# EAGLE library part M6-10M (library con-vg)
CONNECTOR male, 6 pins + 10 coax type C, rows ABC, grid 2.54 mm
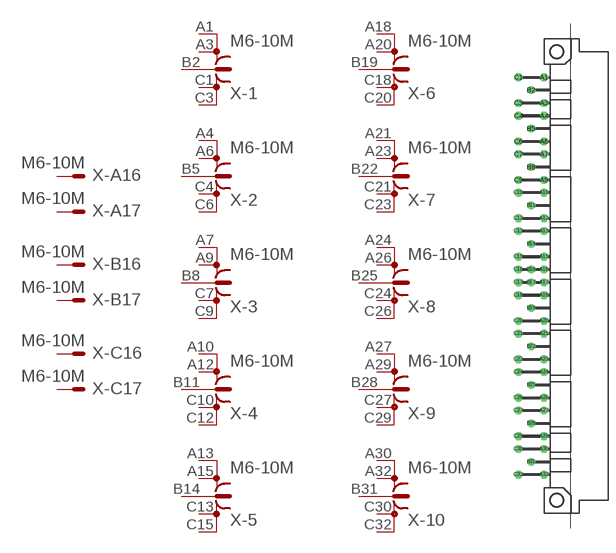
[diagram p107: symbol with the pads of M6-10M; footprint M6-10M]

Designator prefix X; gates -A16=MVAL -A17=MVAL -B16=MVAL -B17=MVAL -C16=MVAL -C17=MVAL -1=COAX -2=COAX -3=COAX -4=COAX -5=COAX -6=COAX -7=COAX -8=COAX -9=COAX -10=COAX

## M6-10M  [M6-10M]
A1  -1:S1  pas
A3  -1:S2  pas
A4  -2:S1  pas
A6  -2:S2  pas
A7  -3:S1  pas
A9  -3:S2  pas
A10  -4:S1  pas
A12  -4:S2  pas
A13  -5:S1  pas
A15  -5:S2  pas
A16  -A16:S  pas
A17  -A17:S  pas
A18  -6:S1  pas
A20  -6:S2  pas
A21  -7:S1  pas
A23  -7:S2  pas
A24  -8:S1  pas
A26  -8:S2  pas
A27  -9:S1  pas
A29  -9:S2  pas
A30  -10:S1  pas
A32  -10:S2  pas
B2  -1:S  pas
B5  -2:S  pas
B8  -3:S  pas
B11  -4:S  pas
B14  -5:S  pas
B16  -B16:S  pas
B17  -B17:S  pas
B19  -6:S  pas
B22  -7:S  pas
B25  -8:S  pas
B28  -9:S  pas
B31  -10:S  pas
C1  -1:S3  pas
C3  -1:S4  pas
C4  -2:S3  pas
C6  -2:S4  pas
C7  -3:S3  pas
C9  -3:S4  pas
C10  -4:S3  pas
C12  -4:S4  pas
C13  -5:S3  pas
C15  -5:S4  pas
C16  -C16:S  pas
C17  -C17:S  pas
C18  -6:S3  pas
C20  -6:S4  pas
C21  -7:S3  pas
C23  -7:S4  pas
C24  -8:S3  pas
C26  -8:S4  pas
C27  -9:S3  pas
C29  -9:S4  pas
C30  -10:S3  pas
C32  -10:S4  pas

## Footprint M6-10M (pad centres in mm)
CONNECTOR male, 6 pins + 10 coax type C, rows ABC, grid 2.54 mm
drill 1.016 octagon: A1 -2.54,39.37; A3 -2.54,34.29; A4 -2.54,31.75; A6 -2.54,26.67; A7 -2.54,24.13; A9 -2.54,19.05; A10 -2.54,16.51; A12 -2.54,11.43; A13 -2.54,8.89; A15 -2.54,3.81; A16 -2.54,1.27; A17 -2.54,-1.27; A18 -2.54,-3.81; A20 -2.54,-8.89; A21 -2.54,-11.43; A23 -2.54,-16.51; A24 -2.54,-19.05; A26 -2.54,-24.13; A27 -2.54,-26.67; A29 -2.54,-31.75; A30 -2.54,-34.29; A32 -2.54,-39.37; B2 -5.08,36.83; B5 -5.08,29.21; B8 -5.08,21.59; B11 -5.08,13.97; B14 -5.08,6.35; B16 -5.08,1.27; B17 -5.08,-1.27; B19 -5.08,-6.35; B22 -5.08,-13.97; B25 -5.08,-21.59; B28 -5.08,-29.21; B31 -5.08,-36.83; C1 -7.62,39.37; C3 -7.62,34.29; C4 -7.62,31.75; C6 -7.62,26.67; C7 -7.62,24.13; C9 -7.62,19.05; C10 -7.62,16.51; C12 -7.62,11.43; C13 -7.62,8.89; C15 -7.62,3.81; C16 -7.62,1.27; C17 -7.62,-1.27; C18 -7.62,-3.81; C20 -7.62,-8.89; C21 -7.62,-11.43; C23 -7.62,-16.51; C24 -7.62,-19.05; C26 -7.62,-24.13; C27 -7.62,-26.67; C29 -7.62,-31.75; C30 -7.62,-34.29; C32 -7.62,-39.37
hole 2.8 at 0,44.45
hole 2.8 at 0,-44.45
